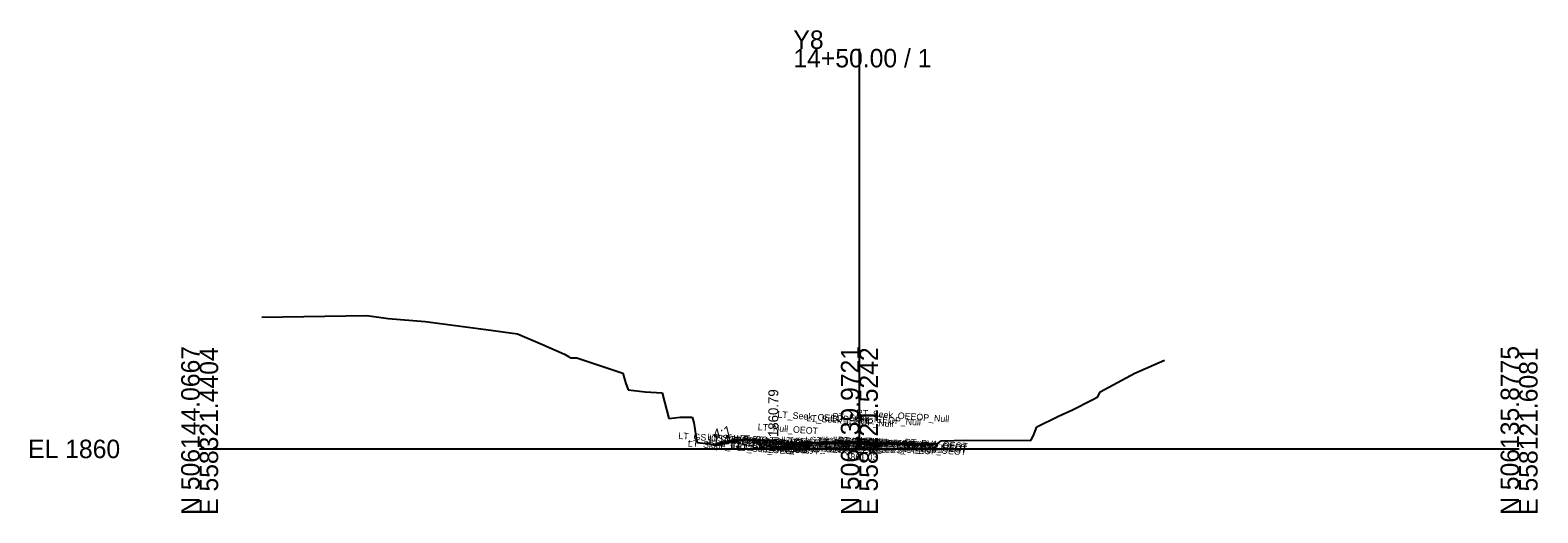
# Model space of a CAD drawing. Extents: x -26 to 203, y -10 to 8070.
# Drawn here: x -25.7 to 202.8, y 4490.3 to 4563.5 of the extents above; entities that cross this region are included whole.
import ezdxf

# ---------------------------------------------------------------- set-up
doc = ezdxf.new("R2010")
doc.units = 0
for name, color, linetype in [('Default', 7, 'Continuous'), ('Exist Cross Section Cell', 7, 'Continuous'), ('Exist XS Center Line Elevation Label', 7, 'Continuous'), ('Exist XS Ground Line', 7, 'Continuous'), ('Prop CMT Conc Surface', 7, 'Continuous'), ('Prop CMT Concrete Structures', 7, 'Continuous'), ('Prop CMT Pvmt Course 1', 7, 'Continuous'), ('Prop CMT Pvmt Course 1 CG', 7, 'Continuous'), ('Prop CMT Pvmt Course 2', 7, 'Continuous'), ('Prop CMT Pvmt Course 3', 7, 'Continuous'), ('Prop CMT Pvmt Surface', 7, 'Continuous'), ('Prop CMT Slope Grass', 7, 'Continuous'), ('Prop CMT Subgrade Earthwork', 7, 'Continuous'), ('Prop XS Earthwork Shape', 7, 'Continuous'), ('Prop XS Hydro Elevations', 7, 'Continuous'), ('Prop XS Side Slope Text', 7, 'Continuous'), ('Typical Text Grade Point CELL', 7, 'Continuous')]:
    doc.layers.add(name, color=color, linetype=linetype)

msp = doc.modelspace()

# ---------------------------------------------------------------- linework, layer by layer
at = {"layer": 'Exist Cross Section Cell'}
for p, q in [((100, 4500), (100, 4560.65)), ((0, 4500), (100, 4500)), ((100, 4500), (200, 4500))]:
    msp.add_line(p, q, dxfattribs=at)
at = {"layer": 'Exist XS Ground Line'}
for p, q in [((9.43, 4519.97), (25.33, 4520.22)), ((25.33, 4520.22), (28.55, 4519.76)), ((28.55, 4519.76), (34.18, 4519.3)), ((34.18, 4519.3), (43.37, 4518.1)), ((43.37, 4518.1), (48.17, 4517.45)), ((48.17, 4517.45), (51.97, 4515.83)), ((51.97, 4515.83), (55.28, 4514.35)), ((55.28, 4514.35), (55.93, 4514.01)), ((55.93, 4514.01), (56.24, 4513.83)), ((56.24, 4513.83), (57.17, 4513.81)), ((57.17, 4513.81), (64.13, 4511.51)), ((64.13, 4511.51), (64.54, 4510.05)), ((136.5, 4508.67), (141.73, 4511.49)), ((141.73, 4511.49), (146.25, 4513.48)), ((64.54, 4510.05), (64.94, 4508.98)), ((64.94, 4508.98), (67.53, 4508.68)), ((67.53, 4508.68), (70.12, 4508.52)), ((70.12, 4508.52), (71.1, 4504.59)), ((132.3, 4505.94), (135.27, 4507.45)), ((135.27, 4507.45), (136.12, 4507.88)), ((136.12, 4507.88), (136.5, 4508.67)), ((71.1, 4504.59), (72.85, 4504.82)), ((72.85, 4504.82), (74.63, 4504.82)), ((74.63, 4504.82), (74.93, 4504.01)), ((126.91, 4503.37), (130.19, 4504.99)), ((130.19, 4504.99), (132.3, 4505.94)), ((74.93, 4504.01), (75.36, 4500.96)), ((126.39, 4502.02), (126.91, 4503.37)), ((75.36, 4500.96), (77.33, 4500.75)), ((77.33, 4500.75), (78.23, 4500.52)), ((78.23, 4500.52), (82.34, 4501.44)), ((82.34, 4501.44), (87.34, 4501.27)), ((87.34, 4501.27), (87.91, 4500.83)), ((87.91, 4500.83), (89.48, 4500.89)), ((89.48, 4500.89), (100.37, 4501.03)), ((100.37, 4501.03), (101.28, 4501.01)), ((101.28, 4501.01), (105.93, 4500.89)), ((105.93, 4500.89), (110.1, 4500.79)), ((110.1, 4500.79), (111.8, 4500.75)), ((111.8, 4500.75), (112.39, 4501.25)), ((112.39, 4501.25), (116.28, 4501.35)), ((116.28, 4501.35), (125.98, 4501.26)), ((125.98, 4501.26), (126.39, 4502.02))]:
    msp.add_line(p, q, dxfattribs=at)
at = {"layer": 'Prop CMT Conc Surface'}
for points in [[(86.95, 4500.79), (86.95, 4501.29), (86.45, 4501.29)], [(88.95, 4500.89), (86.95, 4500.79)]]:
    msp.add_lwpolyline(points, dxfattribs=at)
at = {"layer": 'Prop CMT Concrete Structures'}
for points in [[(88.95, 4500.89), (86.95, 4500.79), (86.95, 4501.29), (86.45, 4501.29)], [(86.45, 4501.29), (86.45, 4500.28), (88.95, 4500.31)], [(88.95, 4500.31), (88.95, 4500.89)]]:
    msp.add_lwpolyline(points, dxfattribs=at)
at = {"layer": 'Prop CMT Pvmt Course 1'}
for points in [[(100, 4501.02), (98, 4501), (97.99, 4501), (94.01, 4500.95), (94, 4500.95), (88.95, 4500.89)], [(88.95, 4500.89), (88.95, 4500.64)], [(88.95, 4500.64), (90.95, 4500.66)], [(100, 4501.02), (102, 4500.99), (102.01, 4500.99), (105.99, 4500.89), (106, 4500.89), (111.04, 4500.76)]]:
    msp.add_lwpolyline(points, dxfattribs=at)
at = {"layer": 'Prop CMT Pvmt Course 1 CG'}
for points in [[(88.95, 4500.31), (85.95, 4500.27), (85.65, 4499.98)], [(85.65, 4499.98), (88.95, 4500.02)], [(88.95, 4500.02), (88.95, 4500.31)]]:
    msp.add_lwpolyline(points, dxfattribs=at)
at = {"layer": 'Prop CMT Pvmt Course 2'}
for points in [[(90.95, 4500.66), (88.95, 4500.64)], [(88.95, 4500.64), (88.95, 4500.39)], [(88.95, 4500.39), (90.95, 4500.41)]]:
    msp.add_lwpolyline(points, dxfattribs=at)
at = {"layer": 'Prop CMT Pvmt Course 3'}
for points in [[(90.95, 4500.41), (88.95, 4500.39)], [(88.95, 4500.39), (88.95, 4500.02)], [(88.95, 4500.02), (90.95, 4500.04)]]:
    msp.add_lwpolyline(points, dxfattribs=at)
at = {"layer": 'Prop CMT Pvmt Surface'}
for points in [[(100, 4501.02), (98, 4501), (97.99, 4501), (94.01, 4500.95), (94, 4500.95), (88.95, 4500.89)], [(100, 4501.02), (102, 4500.99), (102.01, 4500.99), (105.99, 4500.89), (106, 4500.89), (111.04, 4500.76)]]:
    msp.add_lwpolyline(points, dxfattribs=at)
at = {"layer": 'Prop CMT Slope Grass'}
msp.add_lwpolyline([(86.45, 4501.29), (80.95, 4501.4), (77.76, 4500.6)], dxfattribs=at)
at = {"layer": 'Prop CMT Subgrade Earthwork'}
for points in [[(88.95, 4500.02), (85.65, 4499.98), (84.3, 4501.33)], [(90.95, 4500.04), (88.95, 4500.02)], [(90.95, 4500.04), (90.95, 4500.91)]]:
    msp.add_lwpolyline(points, dxfattribs=at)
at = {"layer": 'Prop XS Earthwork Shape'}
for points in [[(82.04, 4501.38), (80.95, 4501.4), (77.84, 4500.62), (78.23, 4500.52)], [(82.04, 4501.38), (82.34, 4501.44), (84.3, 4501.33)], [(86.45, 4501.29), (84.3, 4501.33), (86.95, 4501.29)], [(87.91, 4500.83), (86.95, 4500.79), (86.95, 4501.29), (86.45, 4501.29), (84.3, 4501.33), (85.65, 4499.98), (88.95, 4500.02), (90.95, 4500.04), (90.95, 4500.79), (100, 4500.89), (111.04, 4500.64), (111.04, 4500.76), (110.1, 4500.79), (105.99, 4500.89), (102, 4500.99), (100, 4501.02), (98, 4501), (94.01, 4500.95), (89.48, 4500.89)], [(87.91, 4500.83), (86.95, 4500.79), (86.95, 4501.29), (87.34, 4501.27)], [(100, 4501.02), (100.37, 4501.03), (101.28, 4501.01), (102, 4500.99)]]:
    msp.add_lwpolyline(points, close=True, dxfattribs=at)

# ---------------------------------------------------------------- texts
at = {"layer": 'Default'}
msp.add_text('-', height=0.0001, dxfattribs=at).set_placement((0, 4500))
at = {"layer": 'Exist Cross Section Cell'}
for s, p in [('Y8', (90, 4560.65)), ('14+50.00 / 1', (90, 4557.85)), ('EL 1860', (-26, 4498.6))]:
    msp.add_text(s, height=2.8, dxfattribs=at).set_placement(p)
for s, p in [('N 506144.0667', (0, 4490)), ('E 558321.4404', (2.8, 4490)), ('N 506139.9721', (100, 4490)), ('E 558221.5242', (102.8, 4490)), ('N 506135.8775', (200, 4490)), ('E 558121.6081', (202.8, 4490))]:
    msp.add_text(s, height=2.8, rotation=90, dxfattribs=at).set_placement(p)
at = {"layer": 'Exist XS Center Line Elevation Label'}
msp.add_text('1861.03', height=1, dxfattribs=at).set_placement((97.9, 4498.28))
at = {"layer": 'Prop XS Hydro Elevations'}
msp.add_text('1860.79', height=1.5, rotation=90, dxfattribs=at).set_placement((87.7, 4501.79))
at = {"layer": 'Prop XS Side Slope Text'}
msp.add_text('4:1', height=1.5, rotation=14.0373, dxfattribs=at).set_placement((78.02, 4501.44))
at = {"layer": 'Typical Text Grade Point CELL'}
for s, p in [('LT_Seek_OEEOP_Null', (87.55, 4504.75)), ('LT_Seek_IEEOP_Null', (91.93, 4504.22)), ('RT_Seek_IEEOP_Null', (95.87, 4504.47)), ('RT_Seek_OEEOP_Null', (99.49, 4505)), ('LT_GS_OS_GR_Face_Graphics', (72.53, 4501.52)), ('LT_Sub_Trench_Out_DLT', (76.93, 4501.34)), ('LT_CSLP_Pnt', (77.22, 4501.16)), ('LT_CG_Top_BOC', (81.33, 4501.14)), ('LT_CG_Top_Face', (81.85, 4501.14)), ('LT_Null_OEOT', (84.57, 4502.85)), ('LT_Slope_Fill', (73.98, 4500.37)), ('LT_GS_OS_GR_Face_Graphics1', (77.13, 4500.93)), ('LT_CG_MatchPVSlope_Null', (78.87, 4500.93)), ('LT_CG1_Shelf_Out', (80.42, 4500.16)), ('LT_Sub_OEOP', (81.39, 4499.77)), ('LT_CG_Bot_BOC', (81.47, 4500.13)), ('LT_CG_Top_Gut', (82.11, 4500.63)), ('LT_PV2_OEOT', (84.67, 4500.44)), ('LT_PV3_OEOT', (84.67, 4500.19)), ('LT_Sub_OEOT', (84.69, 4499.81)), ('LT_PV1_OEOT', (84.79, 4500.68)), ('LT_CG_Bot_IE', (84.84, 4500.09)), ('LT_PV_Sub_Tie_Out', (88.14, 4500.86)), ('LT_Null OEEOP Test', (88.39, 4500.88)), ('LT_PV2_OEEOP', (89.36, 4500.52)), ('LT_PV3_OEEOP', (89.36, 4500.27)), ('LT_Sub_OEEOP', (89.39, 4499.9)), ('LT_PV1_OEEOP', (89.48, 4500.64)), ('LT_Pvmt Out', (90.25, 4500.71)), ('LT_Null IEEOP Test', (91.77, 4500.89)), ('LT_PV_Sub_Tie_In', (92.75, 4500.86)), ('LT_PV2_IEEOP', (93.74, 4500.54)), ('LT_PV3_IEEOP', (93.74, 4500.29)), ('LT_Sub_IEEOP', (93.77, 4499.92)), ('LT_PV1_IEEOP', (93.86, 4500.66)), ('Null RT Pvmt Slope', (94.25, 4500.94)), ('Null LT Pvmt Slope', (94.31, 4500.92)), ('PV1_Overlay_Null', (94.75, 4500.76)), ('LT_Pvmt In', (94.84, 4500.72)), ('RT_PV_Sub_Tie_In', (96.69, 4500.86)), ('RT_Null IEEOP Test', (96.71, 4500.88)), ('Sub_PGL', (97.34, 4499.83)), ('PV2_PGL', (97.32, 4500.46)), ('PV3_PGL', (97.32, 4500.21)), ('PV1_PGL', (97.44, 4500.7)), ('RT_PV2_IEEOP', (97.69, 4500.52)), ('RT_PV3_IEEOP', (97.69, 4500.27)), ('RT_Sub_IEEOP', (97.71, 4499.9)), ('RT_PV1_IEEOP', (97.8, 4500.64)), ('RT_Pvmt In', (98.8, 4500.71)), ('CL', (99.19, 4500.6)), ('RT_Null OEEOP Test', (99.33, 4500.83)), ('RT_PV_Sub_Tie_Out', (100.08, 4500.8)), ('RT_PV2_OEEOP', (101.31, 4500.46)), ('RT_PV3_OEEOP', (101.31, 4500.21)), ('RT_Sub_OEEOP', (101.33, 4499.83)), ('RT_PV1_OEEOP', (101.43, 4500.57)), ('RT_Pvmt Out', (102.17, 4500.65)), ('RT_PV2_OEOT', (106.7, 4500.31)), ('RT_PV3_OEOT', (106.7, 4500.06)), ('RT_Sub_OEOT', (106.73, 4499.69)), ('RT_PV1_OEOT', (106.82, 4500.56))]:
    msp.add_text(s, height=1, rotation=356, dxfattribs=at).set_placement(p)

doc.saveas('drawing.dxf')
